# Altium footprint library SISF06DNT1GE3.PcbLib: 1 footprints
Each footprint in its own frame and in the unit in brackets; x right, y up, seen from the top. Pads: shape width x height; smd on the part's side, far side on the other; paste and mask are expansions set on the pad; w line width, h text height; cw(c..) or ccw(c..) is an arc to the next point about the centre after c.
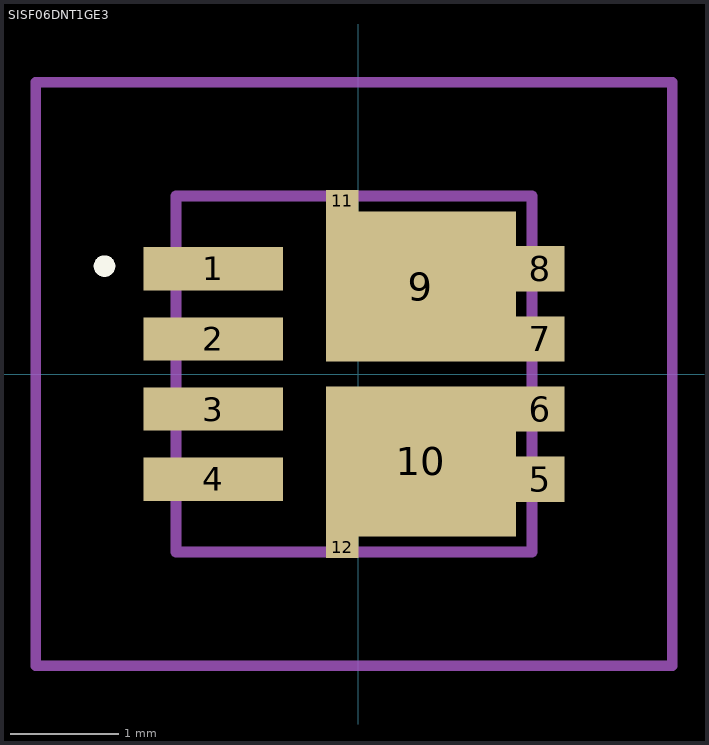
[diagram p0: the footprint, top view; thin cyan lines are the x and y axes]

## SISF06DNT1GE3 [mm]
pads (12):
  rect 1.29x0.4 smd: 1(-1.342,0.975) 2(-1.342,0.325) 3(-1.342,-0.325) 4(-1.342,-0.975)
  rect 0.45x0.42 smd: 5(1.688,-0.975) 6(1.688,-0.325) 7(1.688,0.325) 8(1.688,0.975)
  rect 1.76x1.39 smd: 9(0.583,0.81) 10(0.583,-0.81)
  rect 0.3x0.2 smd: 11(-0.147,1.605) 12(-0.147,-1.605)
Top Overlay:
  lines w0.1: -2.4,1 cw(c-2.35,1) -2.3,1 ; -2.4,1 -2.4,1 ; -2.4,1 ccw(c-2.35,1) -2.3,1 ; -2.3,1 -2.3,1
Mechanical 15:
  lines w0.1: -1.687,-1.65 1.613,-1.65 1.613,1.65 -1.687,1.65 -1.687,-1.65
Mechanical 20:
  lines w0.1: -2.987,-2.705 2.912,-2.705 2.912,2.705 -2.987,2.705 -2.987,-2.705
